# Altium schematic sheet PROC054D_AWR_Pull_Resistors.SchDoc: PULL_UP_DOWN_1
size 558 x 431 mm; Date: Not shown in title block; ApprovedBy: Not shown in title block; CheckedBy: Not shown in title block; Author: Not shown in title block; CompanyName: Not shown in title block; DrawnBy: a0271760; Engineer: Not shown in title block; Organization: Not shown in title block; Address1: Not shown in title block; Address2: Not shown in title block; Address3: Not shown in title block; Address4: Not shown in title block; DocumentNumber: 12; Revision: Use project pAWRameter SCH_Rev; SheetNumber: 12; SheetTotal: 19; PageSetup: Record=PageOptions¦CenterHorizontal=True¦CenterVertical=True¦PrintScale=1.00¦XCorrection=1.00¦YCorrection=1.00¦PrintKind=0¦BorderSize=5000000¦LeftOffset=0¦BottomOffset=0¦Orientation=2¦PaperLength=1000¦PaperWidth=1000¦Scale=100¦PaperSource=15¦PrintQuality=600¦MediaType=1¦DitherType=10¦PaperKind=Letter¦PrintScaleMode=1
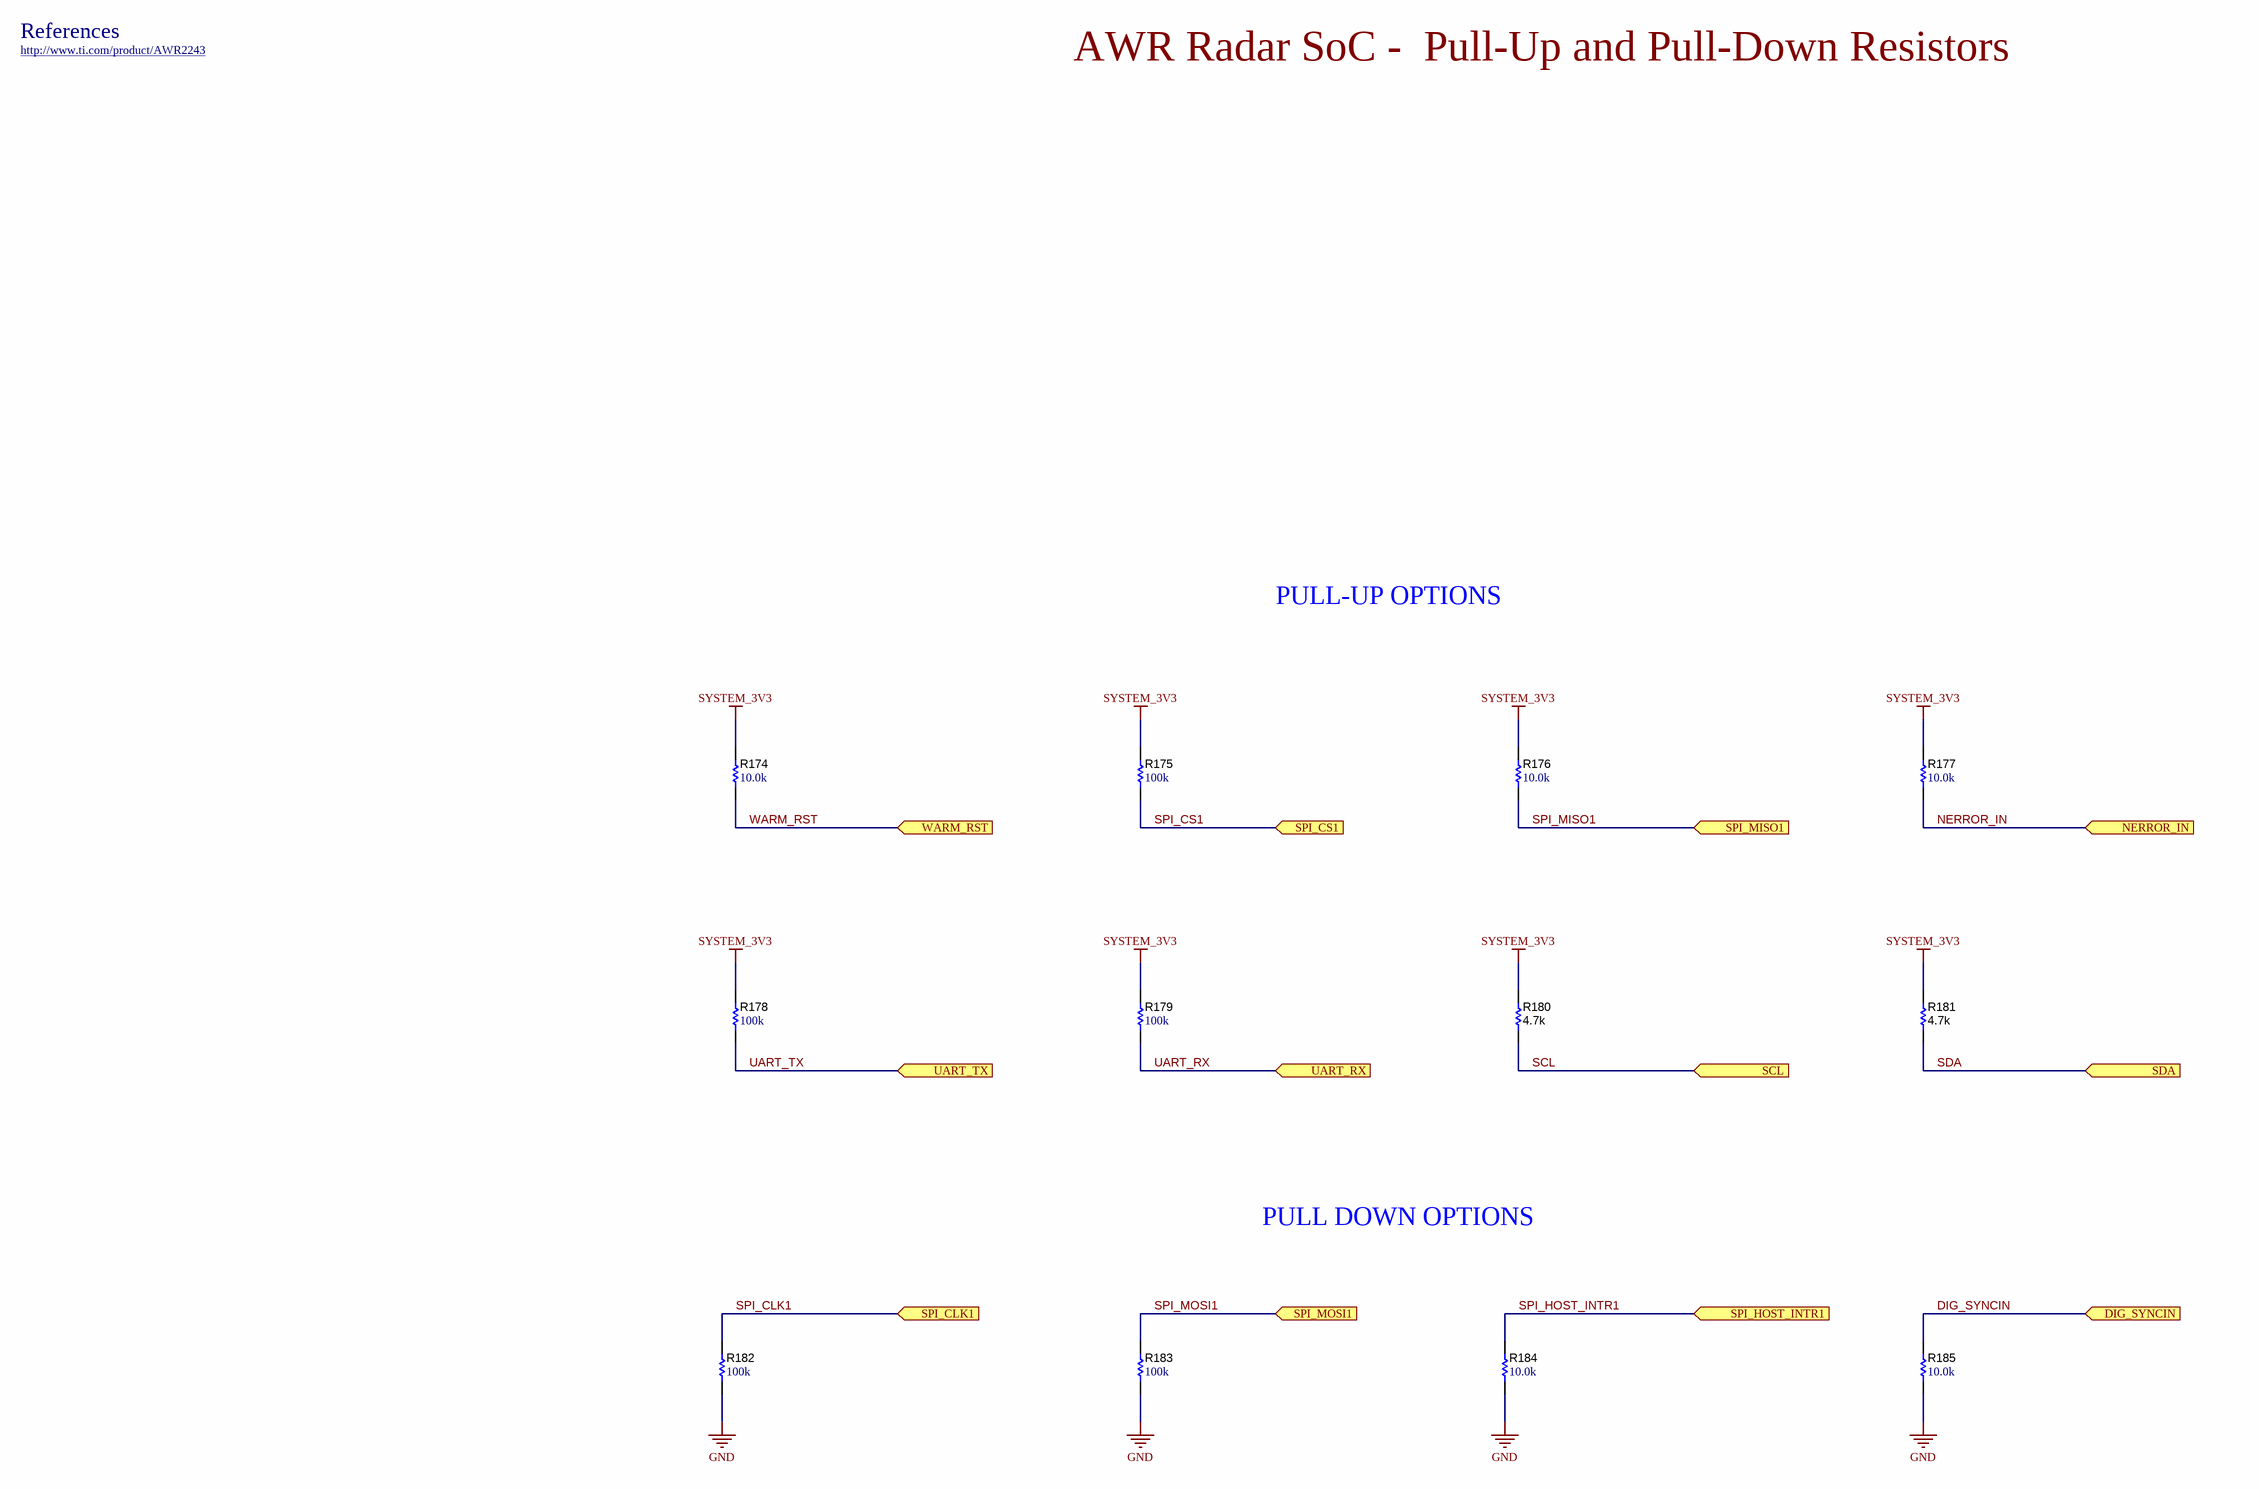
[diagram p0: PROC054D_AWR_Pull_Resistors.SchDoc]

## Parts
R174  ValueDisplayed: 10.0k  [0402]  (hidden comment: CRCW040210K0FKED)
R175  ValueDisplayed: 100k  [0402]  (hidden comment: CRCW0402100KFKED)
R176  ValueDisplayed: 10.0k  [0402]  (hidden comment: CRCW040210K0FKED)
R177  ValueDisplayed: 10.0k  [0402S]  (hidden comment: CRCW040210K0FKED)
R178  ValueDisplayed: 100k  [0402]  (hidden comment: CRCW0402100KFKED)
R179  ValueDisplayed: 100k  [0402]  (hidden comment: CRCW0402100KFKED)
R180  ValueDisplayed: 4.7k  [0402S]  (hidden comment: CRCW04024K70JNED)
R181  ValueDisplayed: 4.7k  [0402S]  (hidden comment: CRCW04024K70JNED)
R182  ValueDisplayed: 100k  [0402]  (hidden comment: CRCW0402100KFKED)
R183  ValueDisplayed: 100k  [0402]  (hidden comment: CRCW0402100KFKED)
R184  ValueDisplayed: 10.0k  [0402]  (hidden comment: CRCW040210K0FKED)
R185  ValueDisplayed: 10.0k  [0402S]  (hidden comment: CRCW040210K0FKED)

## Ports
DIG_SYNCIN (in), NERROR_IN (in), SCL (in), SDA (in), SPI_CLK1 (in), SPI_CS1 (in), SPI_HOST_INTR1 (in), SPI_MISO1 (in), SPI_MOSI1 (in), UART_RX (in), UART_TX (in), WARM_RST (in)

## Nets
GND: R182.1 R183.1 R184.1 R185.1
SYSTEM_3V3: R174.2 R175.2 R176.2 R177.2 R178.2 R179.2 R180.2 R181.2
DIG_SYNCIN: R185.2 ; port DIG_SYNCIN
NERROR_IN: R177.1 ; port NERROR_IN
SCL: R180.1 ; port SCL
SDA: R181.1 ; port SDA
SPI_CLK1: R182.2 ; port SPI_CLK1
SPI_CS1: R175.1 ; port SPI_CS1
SPI_HOST_INTR1: R184.2 ; port SPI_HOST_INTR1
SPI_MISO1: R176.1 ; port SPI_MISO1
SPI_MOSI1: R183.2 ; port SPI_MOSI1
UART_RX: R179.1 ; port UART_RX
UART_TX: R178.1 ; port UART_TX
WARM_RST: R174.1 ; port WARM_RST

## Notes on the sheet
- References
- http://www.ti.com/product/AWR2243
- AWR Radar SoC -  Pull-Up and Pull-Down Resistors
- PULL-UP OPTIONS
- PULL DOWN OPTIONS

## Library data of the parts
R174 R176 R177 R184 R185 = CMP-0025958-3: RES, 10.0 k, 1%, 0.063 W, AEC-Q200 Grade 0, 0402; Manufacturer: Vishay-Dale; Power_W: 63mW; TempCo: 100 ppm/C; Value_Code: 10k0; Value: 10.0k; EIA_Code: E96; Res_ohm: 10k; SizeX_mm: 1; SizeY_mm: 0.5; SizeZ_mm: 0.6; Value2: 0.063W; AEC Qualified: Y; VDC_V: 50V; AEC Category: Q200; AEC Grade: 0
R175 R178 R179 R182 R183 = CMP-0025950-3: RES, 100 k, 1%, 0.063 W, AEC-Q200 Grade 0, 0402; Manufacturer: Vishay-Dale; Power_W: 63mW; TempCo: 100 ppm/C; Value: 100k; EIA_Code: E96; SizeX_mm: 1; SizeY_mm: 0.5; SizeZ_mm: 0.6; Value2: 0.063W; AEC Qualified: Y; VDC_V: 50V; AEC Category: Q200; AEC Grade: 0
R180 R181 = CMP-0026938-5: RES, 4.7 k, 5%, 0.063 W, AEC-Q200 Grade 0, 0402; Manufacturer: Vishay-Dale; Power_W: 63mW; TempCo: 200 ppm/C; Value_Code: 4k70; Value: 4.7k; EIA_Code: E24; SizeX_mm: 1; SizeY_mm: 0.5; SizeZ_mm: 0.6; Value2: 0.063W; AEC Qualified: Y; VDC_V: 50V; AEC Category: Q200; AEC Grade: 0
